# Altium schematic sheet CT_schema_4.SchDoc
size 421 x 246 mm
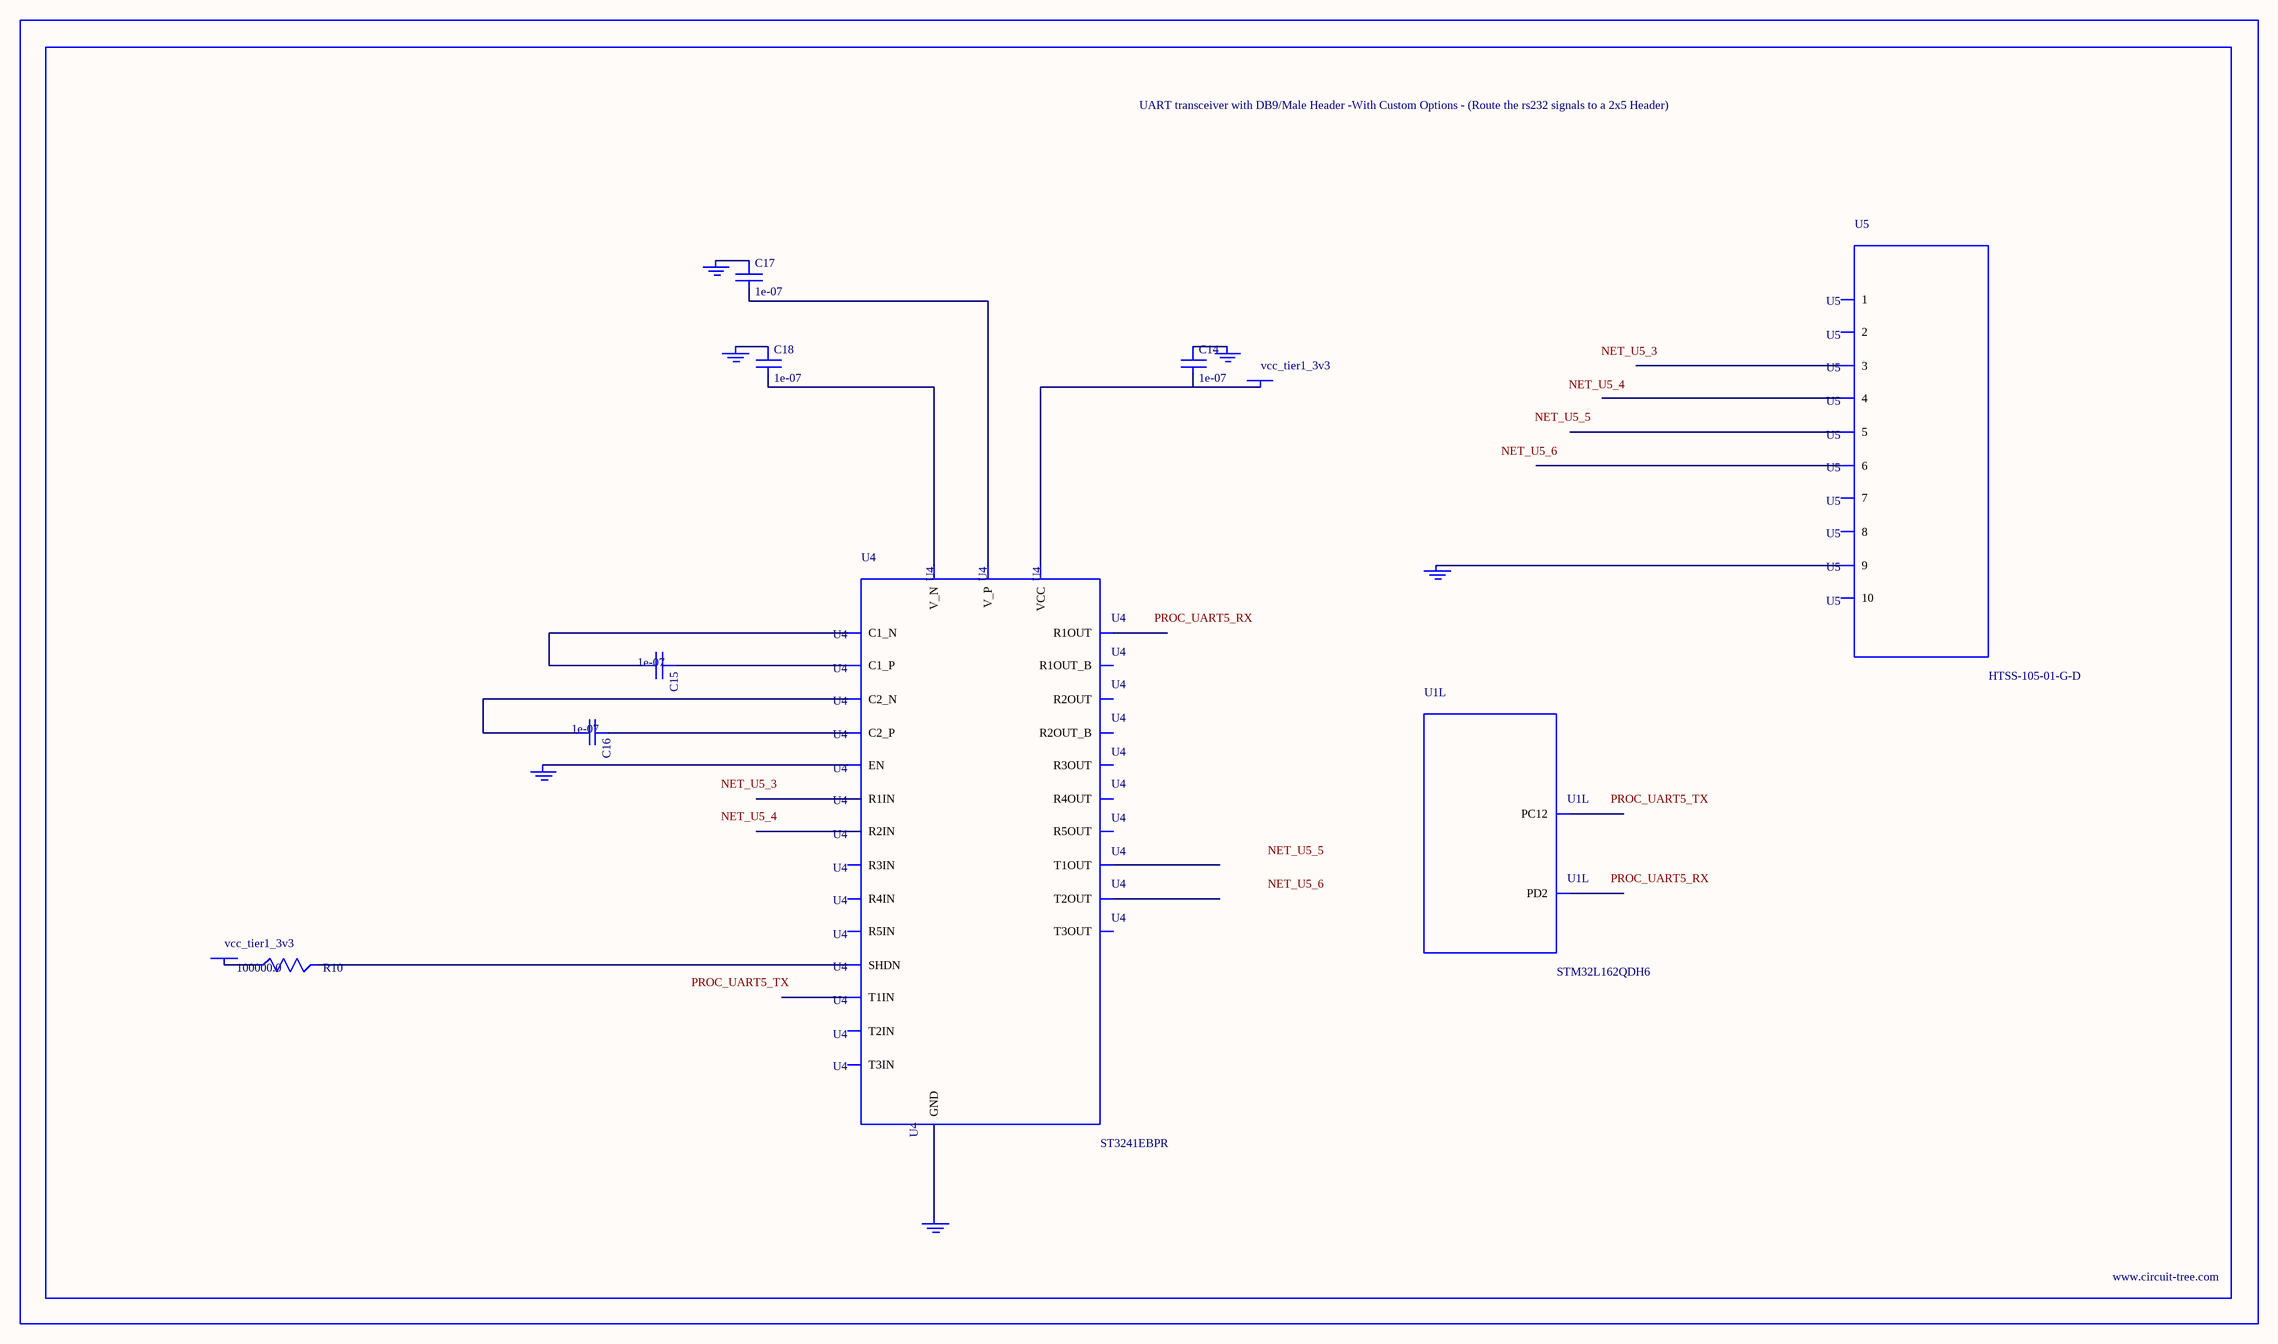
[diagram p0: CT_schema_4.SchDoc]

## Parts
BORDER3  (no value)
C14  1e-07  [C0402]
C15  1e-07  [C0402]
C16  1e-07  [C0402]
C17  1e-07  [C0402]
C18  1e-07  [C0402]
GND_INSTANCE_3_0  (no value)
GND_INSTANCE_3_1  (no value)
GND_INSTANCE_3_2  (no value)
GND_INSTANCE_3_3  (no value)
GND_INSTANCE_3_4  (no value)
GND_INSTANCE_3_5  (no value)
POWER_INSTANCE_3_0  vcc_tier1_3v3
POWER_INSTANCE_3_1  vcc_tier1_3v3
R10  100000.0  [R0603]
U1  STM32L162QDH6  [UFBGA132]  (part L of 12)
U4  ST3241EBPR  [SSOP-28]
U5  HTSS-105-01-G-D  [HTSS-105-01-G-D]

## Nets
NetC14_1: C14.1 GND_INSTANCE_3_2.0(GND)
NetC14_2: C14.2 POWER_INSTANCE_3_1.0(PWR) U4.26(VCC)
NetC15_1: C15.1 U4.28(C1_P)
NetC15_2: C15.2 U4.24(C1_N)
NetC16_1: C16.1 U4.1(C2_P)
NetC16_2: C16.2 U4.2(C2_N)
NetC17_1: C17.1 GND_INSTANCE_3_3.0(GND)
NetC17_2: C17.2 U4.27(V_P)
NetC18_1: C18.1 GND_INSTANCE_3_0.0(GND)
NetC18_2: C18.2 U4.3(V_N)
NetGND_INSTANCE_3_1_0: GND_INSTANCE_3_1.0(GND) U4.23(EN)
NetGND_INSTANCE_3_4_0: GND_INSTANCE_3_4.0(GND) U4.25(GND)
NetGND_INSTANCE_3_5_0: GND_INSTANCE_3_5.0(GND) U5.9
NetPOWER_INSTANCE_3_0_0: POWER_INSTANCE_3_0.0(PWR) R10.1
NetR10_2: R10.2 U4.22(SHDN)

Not connected (* = marked no-connect by the designer): U1 B10(PC12) C8(PD2); U4 4(R1IN) 5(R2IN) 6(R3IN) 7(R4IN) 8(R5IN) 9(T1OUT) 10(T2OUT) 11(T3OUT) 12(T3IN) 13(T2IN) 14(T1IN) 15(R5OUT) 16(R4OUT) 17(R3OUT) 18(R2OUT) 19(R1OUT) 20(R2OUT_B) 21(R1OUT_B); U5 1 2 3 4 5 6 7 8 10

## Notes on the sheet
- Labels drawn without touching a wire or pin: NET_U5_3, NET_U5_4, NET_U5_5, NET_U5_6, PROC_UART5_RX, PROC_UART5_TX

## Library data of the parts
BORDER3 = BORDER_PAGE3
C14-C18 = C0402C104K3RACTU
GND_INSTANCE_3_0-GND_INSTANCE_3_5 = GND
POWER_INSTANCE_3_0 POWER_INSTANCE_3_1 = PWR
R10 = RC0603JR-07100KL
